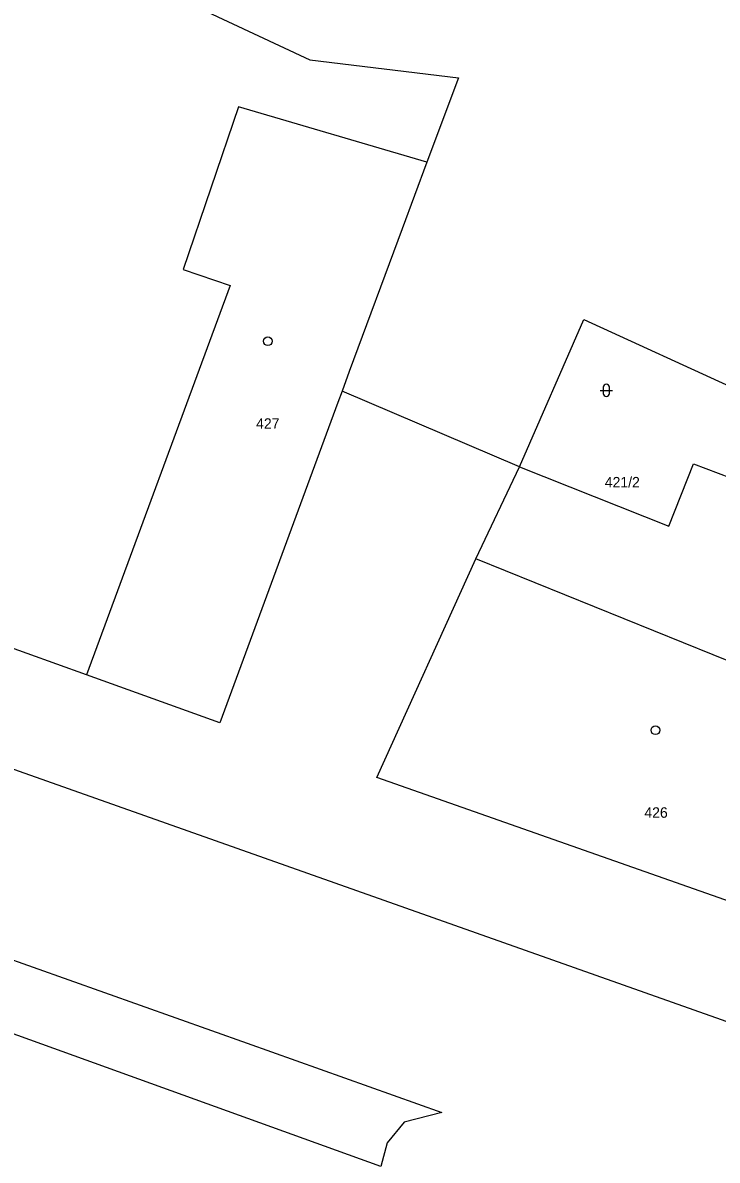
# Model space of a CAD drawing. Extents: x -702257 to -701487, y -1009871 to -1008841.
# Drawn here: x -701595.33 to -701567.14, y -1009063.02 to -1009016.85 of the extents above; entities that cross this region are included whole.
import ezdxf

# ---------------------------------------------------------------- set-up
doc = ezdxf.new("R2010")
doc.units = 0
for name, color, linetype in [('Z_katastr_cisla_pozemkova', 7, 'Continuous'), ('Z_katastr_cisla_stavebni', 7, 'Continuous'), ('Z_katastr_hranice', 7, 'Continuous'), ('Z_katastr_vnitrni_kresba', 7, 'Continuous'), ('Z_katastr_znacky_budov', 7, 'Continuous'), ('Z_katastr_znacky_kultur', 7, 'Continuous')]:
    doc.layers.add(name, color=color, linetype=linetype)

msp = doc.modelspace()

# ---------------------------------------------------------------- linework, layer by layer
at = {"layer": 'Z_katastr_hranice'}
for p, q in [((-701592.58, -1009014.17), (-701583.67, -1009018.36)), ((-701583.67, -1009018.36), (-701577.64, -1009019.09)), ((-701577.64, -1009019.09), (-701578.92, -1009022.51)), ((-701578.92, -1009022.51), (-701579.92, -1009025.21)), ((-701579.92, -1009025.21), (-701582.07, -1009031)), ((-701575.16, -1009034.88), (-701572.55, -1009028.89)), ((-701572.55, -1009028.89), (-701566.29, -1009031.76)), ((-701582.07, -1009031), (-701582.36, -1009031.8)), ((-701582.36, -1009031.8), (-701582.53, -1009032.26)), ((-701575.16, -1009034.88), (-701582.36, -1009031.8)), ((-701582.53, -1009032.26), (-701587.33, -1009045.27)), ((-701576.94, -1009038.61), (-701575.16, -1009034.88)), ((-701575.16, -1009034.88), (-701569.1, -1009037.28)), ((-701569.1, -1009037.28), (-701568.1, -1009034.75)), ((-701568.1, -1009034.75), (-701556.67, -1009039.07)), ((-701627.99, -1009035.71), (-701552.9, -1009062.3)), ((-701580.95, -1009047.48), (-701576.94, -1009038.61)), ((-701592.74, -1009043.32), (-701598.37, -1009041.29)), ((-701587.33, -1009045.27), (-701592.74, -1009043.32)), ((-701580.79, -1009063.28), (-701630.4, -1009045.38)), ((-701620.36, -1009046.16), (-701586.21, -1009058.27)), ((-701560.9, -1009054.54), (-701580.95, -1009047.48)), ((-701586.21, -1009058.27), (-701578.31, -1009061.09)), ((-701578.31, -1009061.09), (-701579.84, -1009061.48)), ((-701579.84, -1009061.48), (-701580.53, -1009062.32)), ((-701580.53, -1009062.32), (-701580.79, -1009063.28))]:
    msp.add_line(p, q, dxfattribs=at)
at = {"layer": 'Z_katastr_vnitrni_kresba'}
for p, q in [((-701586.57, -1009020.26), (-701588.82, -1009026.86)), ((-701578.92, -1009022.51), (-701586.57, -1009020.26)), ((-701588.82, -1009026.86), (-701586.9, -1009027.52)), ((-701586.9, -1009027.52), (-701592.74, -1009043.32)), ((-701562.42, -1009044.49), (-701576.94, -1009038.61))]:
    msp.add_line(p, q, dxfattribs=at)
at = {"layer": 'Z_katastr_znacky_budov'}
for centre in [(-701585.377, -1009029.779), (-701569.647, -1009045.569)]:
    msp.add_circle(centre, 0.175, dxfattribs=at)
at = {"layer": 'Z_katastr_znacky_kultur'}
for p, q in [((-701571.765, -1009031.645), (-701571.765, -1009031.896)), ((-701571.515, -1009031.896), (-701571.515, -1009031.645)), ((-701571.89, -1009031.77), (-701571.39, -1009031.77))]:
    msp.add_line(p, q, dxfattribs=at)
for centre, start, end in [((-701571.64, -1009031.645), 0, 180), ((-701571.64, -1009031.895), 180, 359.9879)]:
    msp.add_arc(centre, 0.125, start, end, dxfattribs=at)

# ---------------------------------------------------------------- texts
at = {"layer": 'Z_katastr_cisla_pozemkova'}
msp.add_text('421/2', height=0.425, dxfattribs=at).set_placement((-701571.699, -1009035.71))
at = {"layer": 'Z_katastr_cisla_stavebni'}
for s, p in [('427', (-701585.853, -1009033.33)), ('426', (-701570.093, -1009049.12))]:
    msp.add_text(s, height=0.425, dxfattribs=at).set_placement(p)

doc.saveas('drawing.dxf')
